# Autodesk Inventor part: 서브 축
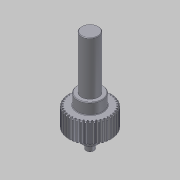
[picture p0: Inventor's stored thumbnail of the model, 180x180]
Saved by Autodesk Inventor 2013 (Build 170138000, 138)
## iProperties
Created: 2013-12
Part Number: 서브 축
Material: 강
Document SubType Name: Modeling
Designer: 한국산업디자인학원
Categories: <?xml version="1.0" encoding="UTF-16"?> <MemberInstance><Categories><FamilyTemplate><FamilyTemplateParameter ValueType="xs:double" Id="1" ObjectReferenceKey="da
Density: 1 g/cm^3
CustomPartVersion: 1
Author: 한국산업디자인학원
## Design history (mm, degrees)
sketch "Sketch1"
  geometry: C1 r 21 at (0, 0)
  constraints: 1 centre point
  dimensions: "d0" = 42 diameter of C1 (= da_da)
extrude "Extrusion1" new body sketch "Sketch1" distance "d1" = 20 (= da_b); taper "d2" = 0 deg
workplane "Work Plane2"
feature "피치 지름" dims "d4" = 10, "d5" = 0
workplane "Work Plane8"
workplane "Work Plane9"
chamfer "모따기1" distance "d49" = 1; stored, may be unused: second distance "d50" = 2, angle "d51" = 45 deg
sketch "스케치3"
  geometry: C1 r 12.5 at (0, 0); 1 further point
  constraints: 1 centre point, 1 coincident
  dimensions: "d52" = 25 diameter of C1
extrude "돌출2" join sketch "스케치3" distance "d53" = 11; taper "d54" = 0 deg
sketch "스케치4"
  geometry: C1 r 8.5 at (0, 0); 1 further point
  constraints: 1 centre point, 1 coincident
  dimensions: "d55" = 17 diameter of C1
extrude "돌출3" join sketch "스케치4" distance "d56" = 53; taper "d57" = 0 deg
sketch "스케치5"
  geometry: C1 r 7.5 at (0, 0); 1 further point
  constraints: 1 centre point, 1 coincident
  dimensions: "d62" = 15 diameter of C1
extrude "돌출4" join sketch "스케치5" distance "d63" = 11; taper "d64" = 0 deg
sketch "스케치6"
  geometry: C1 r 4 at (0, 0); 1 further point
  constraints: 1 centre point, 1 coincident
  dimensions: "d65" = 8 diameter of C1
extrude "돌출5" join sketch "스케치6" distance "d66" = 7; taper "d67" = 0 deg
chamfer "모따기2" distance "d58" = 0.5; stored, may be unused: second distance "d59" = 2, angle "d60" = 45 deg
fillet "모깎기1" dims "d61" = 0.5
feature "스퍼 기어" dims "da_b" = 20, "da_d" = 40, "da_aw" = 31, "da_da" = 42, "da_df" = 37.5, "da_dw" = 40, angle "da_beta" = 0 deg, "da_lefttooth" = 0, "da_righttooth" = 0
body "Solid1"
sketch "Sketch2"
  geometry: C1 r 21 at (0, 0) reference; C2 r 20 at (0, 0)
  constraints: 1 centre point, 1 coincident
  dimensions: "d3" = 40 diameter of C2 (= da_dw)
body "Srf1"
other parameters: "d16" = 31 (= da_aw), "d17" = 0, "d34" = 4.5 deg (computed from da_z), "d39" = 0, "d41" = 0, "d43" = 31 (= da_aw), "d46" = 31 (= da_aw), "d47" = 0, "d48" = 0
